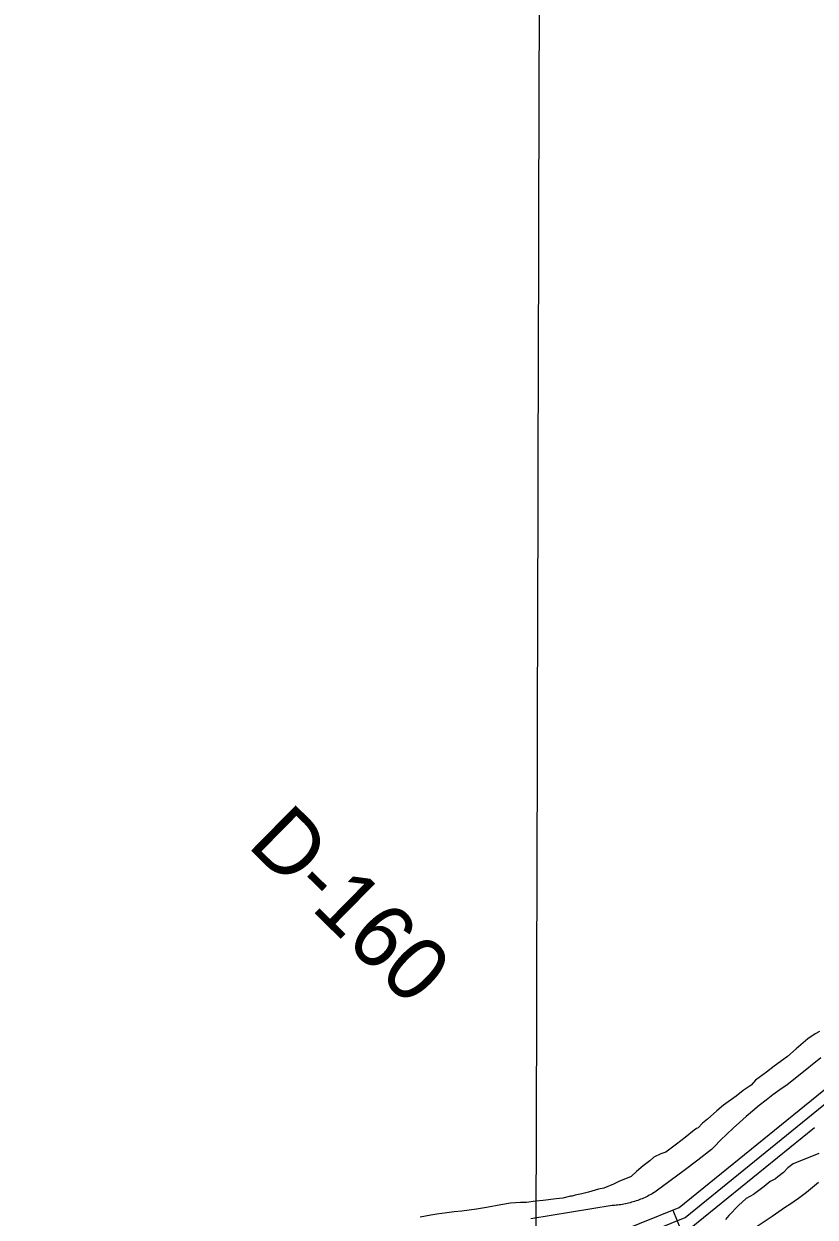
# Model space of a CAD drawing. Extents: x 3180038 to 3217926, y 922069 to 947485.
# Drawn here: x 3186224 to 3187258, y 935201 to 936760 of the extents above; entities that cross this region are included whole.
import ezdxf

# ---------------------------------------------------------------- set-up
doc = ezdxf.new("R2010")
doc.units = 0
for name, color, linetype in [('V-GRID-MAJR', 7, 'Continuous'), ('V-LEVE-TOET', 7, 'Continuous'), ('V-RIVR-RANG-IDEN', 7, 'Continuous'), ('V-ROAD-CNTR', 7, 'Continuous'), ('V-SITE-VEGE', 7, 'Continuous')]:
    doc.layers.add(name, color=color, linetype=linetype)

msp = doc.modelspace()

# ---------------------------------------------------------------- linework, layer by layer
at = {"layer": 'V-GRID-MAJR'}
msp.add_spline([(3186873.701, 927512.849), (3186889.572, 933574.8250000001), (3186905.4450000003, 939637.892), (3186921.319, 945701.009), (3186921.322, 945702.052)], degree=3, dxfattribs=at)
at = {"layer": 'V-LEVE-TOET'}
for points in [[(3187265.756000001, 935409.0589999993), (3187236.439000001, 935385.6119999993), (3187221.495000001, 935373.9519999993), (3187221.495000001, 935373.9519999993), (3187212.271000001, 935367.3859999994), (3187203.163000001, 935360.6629999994), (3187194.172000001, 935353.7819999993), (3187185.302000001, 935346.7469999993), (3187176.558000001, 935339.5579999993), (3187167.937000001, 935332.2199999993), (3187159.444000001, 935324.7329999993), (3187151.084000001, 935317.0999999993), (3187142.858000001, 935309.3259999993), (3187134.768000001, 935301.4079999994), (3187126.816000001, 935293.3529999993), (3187122.845000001, 935289.2219999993), (3187122.845000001, 935289.2219999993), (3187104.978000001, 935275.4599999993), (3187086.988000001, 935261.8369999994), (3187068.884000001, 935248.3529999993)], [(3187068.884000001, 935248.3529999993), (3187050.669000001, 935235.0139999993), (3187048.7150000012, 935233.5969999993), (3187048.7150000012, 935233.5969999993), (3187046.944000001, 935232.5239999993), (3187045.154000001, 935231.4789999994), (3187043.347000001, 935230.4689999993), (3187041.521000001, 935229.4879999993), (3187039.679000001, 935228.5399999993), (3187037.820000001, 935227.6249999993), (3187035.946000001, 935226.7419999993), (3187034.058000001, 935225.8919999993), (3187032.153000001, 935225.0749999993), (3187030.236000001, 935224.2909999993), (3187028.305000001, 935223.5409999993), (3187026.361000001, 935222.8239999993), (3187024.403000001, 935222.1419999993), (3187022.437000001, 935221.4929999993), (3187020.457000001, 935220.8789999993), (3187018.468000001, 935220.3009999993), (3187016.469000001, 935219.7559999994), (3187014.460000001, 935219.2459999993), (3187012.445000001, 935218.7709999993), (3187010.420000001, 935218.3329999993), (3187008.388000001, 935217.9299999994), (3187006.348000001, 935217.5609999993), (3187004.304000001, 935217.2269999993), (3187002.254000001, 935216.9319999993), (3187000.198000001, 935216.6699999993), (3186998.138000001, 935216.4449999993), (3186996.075000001, 935216.2559999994), (3186994.009000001, 935216.1029999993), (3186992.864000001, 935216.0329999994), (3186992.864000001, 935216.0329999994), (3186886.974000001, 935198.6049999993)], [(3187182.462000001, 935189.2799999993), (3187202.248000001, 935202.3789999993), (3187219.5530000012, 935214.2389999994), (3187219.5530000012, 935214.2389999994), (3187225.189000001, 935217.9299999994), (3187230.760000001, 935221.7179999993), (3187236.263000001, 935225.6029999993), (3187241.698000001, 935229.5849999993), (3187247.062000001, 935233.6579999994), (3187252.356000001, 935237.8259999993), (3187257.574000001, 935242.0859999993), (3187262.719000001, 935246.4359999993)]]:
    msp.add_lwpolyline(points, dxfattribs=at)
at = {"layer": 'V-ROAD-CNTR'}
msp.add_line((3187072.2418186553, 935209.994552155), (3187083.4257962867, 935182.1576078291), dxfattribs=at)
for points in [[(3186059.779843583, 935066.3108395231), (3186493.6649758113, 935122.577726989), (3186977.0350090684, 935171.7436286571), (3187080.681801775, 935213.3855453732), (3187378.0722069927, 935454.9850621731), (3187701.751559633, 935784.2974035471), (3187785.6833917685, 935880.7022107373), (3187986.2949905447, 936148.3586754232), (3187986.867989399, 936149.080673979), (3188025.2569126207, 936198.8875743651), (3188062.511838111, 936248.864474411), (3188098.9567652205, 936299.6183729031), (3188134.337694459, 936351.4092693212), (3188168.939625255, 936403.2551656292), (3188202.7115577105, 936455.8470604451), (3188235.416492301, 936509.4719531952), (3188267.3424284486, 936563.1558458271), (3188298.274366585, 936617.2687376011), (3188328.316306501, 936672.7506266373), (3188446.4690701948, 936871.6422288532)], [(3184281.969399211, 935074.670822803), (3185479.173004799, 935059.6338528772), (3186060.640841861, 935051.2968695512), (3186495.3889723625, 935107.675756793), (3186980.661001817, 935157.0346580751), (3187088.378786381, 935200.3125715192), (3187388.1811867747, 935443.8720843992), (3187712.766537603, 935774.1064239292), (3187797.357368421, 935871.2672296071), (3187998.169966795, 936139.1926937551)], [(3184281.929399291, 935059.6698528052), (3185478.9710052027, 935044.6348828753), (3186061.501840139, 935036.282899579), (3186497.112968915, 935092.7737865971), (3186984.2869945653, 935142.3256874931), (3187096.0757709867, 935187.2395976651), (3187257.292448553, 935318.2123357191)]]:
    msp.add_lwpolyline(points, dxfattribs=at)
at = {"layer": 'V-SITE-VEGE'}
for p, q in [((3187248.784, 935433.9059999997), (3187233.646, 935420.5999999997)), ((3187258.174, 935440.5799999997), (3187248.784, 935433.9059999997)), ((3187263.968, 935443.568), (3187258.174, 935440.5799999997)), ((3187233.646, 935420.5999999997), (3187222.105, 935410.98)), ((3187222.105, 935410.98), (3187204.773, 935398.377)), ((3187194.67, 935390.2339999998), (3187180.225, 935379.8529999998)), ((3187204.773, 935398.377), (3187194.67, 935390.2339999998)), ((3187174.477, 935373.221), (3187164.356, 935366.5369999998)), ((3187180.225, 935379.8529999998), (3187174.477, 935373.221)), ((3187154.9760000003, 935359.1309999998), (3187138.362, 935347.2649999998)), ((3187164.356, 935366.5369999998), (3187154.9760000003, 935359.1309999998)), ((3187129.71, 935339.8699999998), (3187117.458, 935328.7859999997)), ((3187138.362, 935347.2649999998), (3187129.71, 935339.8699999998)), ((3187117.458, 935328.7859999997), (3187110.964, 935323.6019999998)), ((3187100.143, 935314.7239999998), (3187088.602, 935305.1070000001)), ((3187103.0300000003, 935316.9459999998), (3187100.143, 935314.7239999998)), ((3187105.207, 935317.702), (3187103.0300000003, 935316.9459999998)), ((3187110.964, 935323.6019999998), (3187105.207, 935317.702)), ((3187077.053, 935296.2159999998), (3187063.336, 935285.8429999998)), ((3187088.602, 935305.1070000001), (3187077.053, 935296.2159999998)), ((3187047.386, 935279.0869999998), (3187042.342, 935274.6510000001)), ((3187056.805, 935283.5759999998), (3187047.386, 935279.0869999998)), ((3187063.336, 935285.8429999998), (3187056.805, 935283.5759999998)), ((3187263.04, 935283.9569999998), (3187229.6850000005, 935270.4259999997)), ((3187033.679, 935267.9849999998), (3187025.026, 935260.5889999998)), ((3187042.342, 935274.6510000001), (3187033.679, 935267.9849999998)), ((3187222.4610000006, 935265.2320000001), (3187216.707, 935259.3319999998)), ((3187229.6850000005, 935270.426), (3187222.4610000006, 935265.2320000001)), ((3187002.592, 935247.9199999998), (3186994.6210000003, 935244.179)), ((3187012.75, 935251.691), (3187002.592, 935247.9199999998)), ((3187017.821, 935253.9419999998), (3187012.75, 935251.691)), ((3187025.026, 935260.5889999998), (3187017.821, 935253.9419999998)), ((3187199.3620000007, 935247.456), (3187191.43, 935240.7979999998)), ((3187206.6040000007, 935251.1889999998), (3187199.3620000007, 935247.456)), ((3187209.491, 935253.4109999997), (3187206.6040000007, 935251.1889999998)), ((3187216.707, 935259.3319999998), (3187209.491, 935253.4109999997)), ((3186953.244, 935231.2739999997), (3186944.517, 935229.7079999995)), ((3186961.96, 935233.5679999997), (3186953.244, 935231.2739999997)), ((3186975.0300000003, 935237.3749999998), (3186961.96, 935233.5679999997)), ((3186982.299, 935238.9239999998), (3186975.0300000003, 935237.3749999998)), ((3186994.6210000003, 935244.179), (3186982.299, 935238.924)), ((3187177.7130000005, 935230.4239999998), (3187168.3020000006, 935225.2059999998)), ((3187191.4300000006, 935240.7979999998), (3187177.7130000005, 935230.4239999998)), ((3186847.753, 935216.8419999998), (3186828.844, 935213.6919999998)), ((3186860.113, 935219.1830000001), (3186847.753, 935216.8420000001)), ((3186873.22, 935220.076), (3186860.113, 935219.1830000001)), ((3186881.236, 935220.174), (3186873.22, 935220.076)), ((3186892.875, 935221.7779999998), (3186881.236, 935220.1739999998)), ((3186903.068, 935222.6339999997), (3186892.875, 935221.7779999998)), ((3186919.8000000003, 935225.0279999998), (3186903.068, 935222.6339999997)), ((3186928.532, 935225.8659999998), (3186919.8000000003, 935225.0279999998)), ((3186938.707, 935228.1799999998), (3186928.532, 935225.8659999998)), ((3186940.892, 935228.2039999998), (3186938.707, 935228.1799999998)), ((3186944.517, 935229.708), (3186940.892, 935228.2039999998)), ((3187158.2120000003, 935216.3339999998), (3187145.2600000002, 935203.0569999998)), ((3187168.3020000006, 935225.2059999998), (3187158.2120000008, 935216.3339999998)), ((3186756.099, 935203.313), (3186742.281, 935200.956)), ((3186764.094, 935204.8689999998), (3186756.099, 935203.313)), ((3186777.191, 935206.491), (3186764.094, 935204.8689999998)), ((3186786.647, 935208.0659999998), (3186777.191, 935206.491)), ((3186796.84, 935208.9219999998), (3186786.647, 935208.0659999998)), ((3186815.753, 935211.3429999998), (3186796.84, 935208.9219999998)), ((3186828.844, 935213.6919999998), (3186815.753, 935211.3429999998)), ((3187145.2600000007, 935203.0569999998), (3187140.9510000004, 935197.9019999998))]:
    msp.add_line(p, q, dxfattribs=at)

# ---------------------------------------------------------------- texts
at = {"layer": 'V-RIVR-RANG-IDEN'}
msp.add_text('D-160', height=82.99999800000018, rotation=315.46359172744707, dxfattribs=at).set_placement((3186514.774, 935686.0580000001))

doc.saveas('drawing.dxf')
